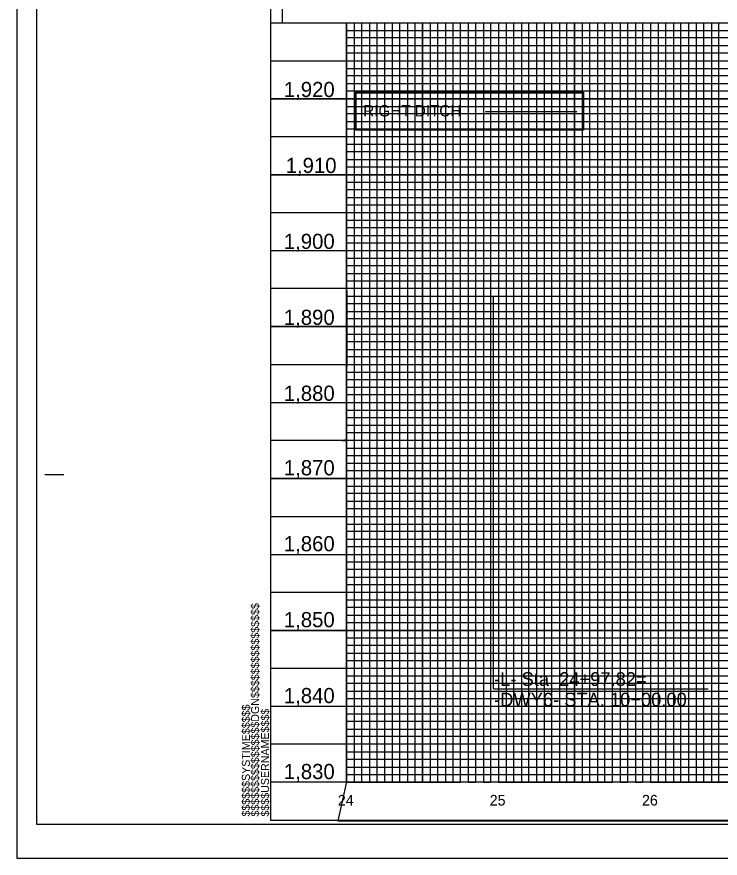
# Model space of a CAD drawing. Extents: x 557032 to 558716, y 513430 to 514605.
# Drawn here: x 557032 to 557495, y 513430 to 513984 of the extents above; entities that cross this region are included whole.
import ezdxf

# ---------------------------------------------------------------- set-up
doc = ezdxf.new("R2010")
doc.units = 0
for name, color, linetype in [('Exist Vertical Profile Horizontal Axis Label Major', 7, 'Continuous'), ('Exist Vertical Profile Vertical Axis Label', 7, 'Continuous'), ('Prop Grid Mask', 7, 'Continuous'), ('Prop PFL Ditch Label CELL', 7, 'Continuous'), ('Prop VPI Label', 7, 'Continuous'), ('Scratch_Level_5', 7, 'Continuous'), ('Sheet Cutting Line CELL', 7, 'Continuous'), ('Sheet DOT Grid CELL', 7, 'Continuous'), ('Sheet Layout Profile Border Port 2', 7, 'Continuous'), ('Sheet Plot Border Inside CELL', 7, 'Continuous'), ('Sheet Plot Border Outside CELL', 7, 'Continuous'), ('Sheet Profile CELL', 7, 'Continuous'), ('Sheet Profile Grid Major CELL', 7, 'Continuous'), ('Sheet Profile Grid Middle CELL', 7, 'Continuous'), ('Sheet Profile Grid Minor CELL', 7, 'Continuous')]:
    doc.layers.add(name, color=color, linetype=linetype)

msp = doc.modelspace()

# ---------------------------------------------------------------- linework, layer by layer
at = {"layer": 'Prop Grid Mask'}
msp.add_lwpolyline([(557255.39, 513934.64), (557405.39, 513934.64), (557405.39, 513909.64), (557255.39, 513909.64)], close=True, dxfattribs=at)
at = {"layer": 'Prop PFL Ditch Label CELL'}
for p, q in [((557255.39, 513919.64), (557255.39, 513919.64)), ((557340.94, 513921.99), (557400.94, 513921.99))]:
    msp.add_line(p, q, dxfattribs=at)
at = {"layer": 'Prop VPI Label'}
for q in [(557346.08, 513800.39), (557487.33, 513541.93)]:
    msp.add_line((557346.08, 513541.93), q, dxfattribs=at)
msp.add_lwpolyline([(557255.7, 513934.19), (557404.36, 513934.19), (557404.36, 513909.98), (557255.7, 513909.98)], close=True, dxfattribs=at)
at = {"layer": 'Scratch_Level_5'}
msp.add_line((557249.45, 513953.77), (557249.38, 513953.77), dxfattribs=at)
for points in [[(557207.08, 514505.4), (557207.08, 513980.4), (558649.45, 513980.4), (558649.45, 514344.35), (558499.4, 514344.35), (558499.4, 514505.4)], [(557249.45, 513960.4), (557249.45, 513809.09), (557249.45, 513808.44), (557249.5, 513800.29), (557249.4, 513708.16), (557249.4, 513480.77), (557243.76, 513454.91), (558646.31, 513455.07), (558649.46, 513648.82), (558649.45, 513648.95), (558649.45, 513655.65), (558652.01, 513799.51), (558499.4, 513799.35), (558499.4, 513960.4)]]:
    msp.add_lwpolyline(points, close=True, dxfattribs=at)
for points in [[(557249.38, 513953.77), (557249.48, 513844.15), (557249.43, 513801.01), (557249.45, 513705.73), (557246.58, 513705.4)], [(557246.58, 513705.4), (557249.45, 513705.4), (557249.45, 513953.77)]]:
    msp.add_lwpolyline(points, dxfattribs=at)
at = {"layer": 'Sheet Cutting Line CELL'}
for p, q in [((557032.45, 514530.4), (557032.45, 513430.4)), ((557032.45, 513430.4), (558716.45, 513430.4))]:
    msp.add_line(p, q, dxfattribs=at)
at = {"layer": 'Sheet DOT Grid CELL'}
for p, q in [((557199.45, 513980.4), (558699.34, 513980.4)), ((557249.45, 513980.4), (557249.45, 513480.4)), ((557299.45, 513980.4), (557299.45, 513480.4)), ((557349.45, 513980.4), (557349.45, 513480.4)), ((557399.45, 513980.4), (557399.45, 513480.4)), ((557449.45, 513980.4), (557449.45, 513480.4)), ((557249.45, 513953.77), (557249.45, 513482.78)), ((557299.45, 513953.77), (557299.45, 513484.02)), ((557349.45, 513953.77), (557349.45, 513484.06)), ((557399.45, 513953.77), (557399.45, 513484.1)), ((557449.45, 513953.77), (557449.45, 513484.13)), ((557199.45, 513930.4), (558699.34, 513930.4)), ((557205.68, 513930.4), (558692.7, 513930.4)), ((557199.45, 513880.4), (558699.34, 513880.4)), ((557205.25, 513880.4), (558692.98, 513880.4)), ((557199.45, 513830.4), (558699.34, 513830.4)), ((557204.83, 513830.4), (558693.26, 513830.4)), ((557199.45, 513780.4), (558699.34, 513780.4)), ((557204.41, 513780.4), (558693.53, 513780.4)), ((557199.45, 513730.4), (558699.34, 513730.4)), ((557203.99, 513730.4), (558693.81, 513730.4)), ((557199.45, 513680.4), (558699.34, 513680.4)), ((557203.57, 513680.4), (558694.09, 513680.4)), ((557199.45, 513630.4), (558699.34, 513630.4)), ((557203.15, 513630.4), (558694.37, 513630.4)), ((557199.45, 513580.4), (558699.34, 513580.4)), ((557202.73, 513580.4), (558694.65, 513580.4)), ((557199.45, 513530.4), (558699.34, 513530.4)), ((557202.31, 513530.4), (558694.93, 513530.4))]:
    msp.add_line(p, q, dxfattribs=at)
at = {"layer": 'Sheet Layout Profile Border Port 2'}
msp.add_lwpolyline([(557249.45, 513980.4), (558649.45, 513980.4), (558649.45, 513480.4), (557249.45, 513480.4)], close=True, dxfattribs=at)
at = {"layer": 'Sheet Plot Border Inside CELL'}
msp.add_lwpolyline([(557045.45, 513452.85), (558711.95, 513452.85), (558711.95, 514507.95), (557045.45, 514507.95)], close=True, dxfattribs=at)
at = {"layer": 'Sheet Plot Border Outside CELL'}
msp.add_lwpolyline([(557032.45, 513430.4), (558716.45, 513430.4), (558716.45, 514530.4), (557032.45, 514530.4)], close=True, dxfattribs=at)
at = {"layer": 'Sheet Profile CELL'}
for p, q in [((557199.45, 513980.4), (558699.45, 513980.4)), ((557050.95, 513682.9), (557063.45, 513682.9)), ((558699.45, 513480.4), (557199.45, 513480.4)), ((557199.45, 513455.4), (558699.45, 513455.4)), ((557199.45, 513455.4), (557199.45, 513455.4)), ((557199.45, 513455.4), (557199.45, 513455.4)), ((557199.45, 513455.4), (557199.45, 513455.4)), ((557199.45, 513455.4), (557199.45, 513455.4)), ((557199.45, 513455.4), (557199.45, 513455.4)), ((557199.45, 513455.4), (557199.45, 513455.4)), ((557199.45, 513455.4), (557199.45, 513455.4))]:
    msp.add_line(p, q, dxfattribs=at)
msp.add_lwpolyline([(558699.45, 514505.4), (557199.45, 514505.4), (557199.45, 513455.4), (558699.45, 513455.4)], close=True, dxfattribs=at)
msp.add_lwpolyline([(557236.95, 513455.4), (557236.95, 513455.4)], dxfattribs=at)
at = {"layer": 'Sheet Profile Grid Major CELL'}
msp.add_line((557199.45, 513480.4), (557199.45, 513480.4), dxfattribs=at)
for points in [[(557249.45, 513980.4), (557249.45, 513480.4), (557299.45, 513480.4), (557299.45, 513980.4), (557349.45, 513980.4), (557349.45, 513480.4), (557399.45, 513480.4), (557399.45, 513980.4), (557449.45, 513980.4), (557449.45, 513480.4), (557499.45, 513480.4)], [(557249.45, 513953.77), (557249.45, 513482.78)], [(557299.45, 513484.02), (557299.45, 513953.77)], [(557349.45, 513953.77), (557349.45, 513484.06)], [(557399.45, 513484.1), (557399.45, 513953.77)], [(557449.45, 513953.77), (557449.45, 513484.13)], [(558699.45, 513930.4), (557199.45, 513930.4)], [(558692.7, 513930.4), (557205.68, 513930.4)], [(558699.45, 513880.4), (557199.45, 513880.4), (557199.45, 513830.4), (558699.45, 513830.4)], [(558692.98, 513880.4), (557205.25, 513880.4)], [(557204.83, 513830.4), (558693.26, 513830.4)], [(558699.45, 513780.4), (557199.45, 513780.4), (557199.45, 513730.4), (558699.45, 513730.4)], [(558693.53, 513780.4), (557204.41, 513780.4)], [(557203.99, 513730.4), (558693.81, 513730.4)], [(558699.45, 513680.4), (557199.45, 513680.4), (557199.45, 513630.4), (558529.45, 513630.4)], [(558694.09, 513680.4), (557203.57, 513680.4)], [(557203.15, 513630.4), (558529.45, 513630.4)], [(558699.45, 513580.4), (557199.45, 513580.4), (557199.45, 513580.4), (557199.45, 513530.4), (558699.45, 513530.4)], [(558694.65, 513580.4), (557202.73, 513580.4)], [(557202.31, 513530.4), (558694.93, 513530.4)], [(558699.45, 513480.4), (557199.45, 513480.4)]]:
    msp.add_lwpolyline(points, dxfattribs=at)
at = {"layer": 'Sheet Profile Grid Middle CELL'}
for points in [[(557224.45, 513980.4), (557274.45, 513980.4), (557274.45, 513480.4), (557324.45, 513480.4), (557324.45, 513980.4), (557374.45, 513980.4), (557374.45, 513480.4), (557424.45, 513480.4), (557424.45, 513980.4), (557474.45, 513980.4), (557474.45, 513480.4), (557524.45, 513480.4)], [(557199.45, 513955.4), (558699.45, 513955.4)], [(557274.45, 513953.77), (557274.45, 513484)], [(557324.45, 513484.04), (557324.45, 513953.77)], [(557374.45, 513953.77), (557374.45, 513484.08)], [(557424.45, 513484.11), (557424.45, 513953.77)], [(557474.45, 513953.77), (557474.45, 513484.15)], [(558699.45, 513905.4), (557199.45, 513905.4), (557199.45, 513855.4), (558699.45, 513855.4)], [(558692.84, 513905.4), (557205.47, 513905.4)], [(557205.04, 513855.4), (558693.12, 513855.4)], [(558699.45, 513805.4), (557199.45, 513805.4), (557199.45, 513755.4), (558699.45, 513755.4)], [(558693.39, 513805.4), (557204.62, 513805.4)], [(557204.2, 513755.4), (558693.67, 513755.4)], [(558699.45, 513705.4), (557199.45, 513705.4), (557199.45, 513655.4), (558699.45, 513655.4)], [(558693.95, 513705.4), (557203.78, 513705.4)], [(557203.36, 513655.4), (558694.23, 513655.4)], [(558699.45, 513605.4), (557199.45, 513605.4), (557199.45, 513555.4), (558699.45, 513555.4)], [(558694.51, 513605.4), (557202.94, 513605.4)], [(557202.52, 513555.4), (558694.79, 513555.4)], [(558699.45, 513505.4), (557199.45, 513505.4)], [(558450.15, 513505.4), (557202.1, 513505.4)]]:
    msp.add_lwpolyline(points, dxfattribs=at)
at = {"layer": 'Sheet Profile Grid Minor CELL'}
for p, q in [((557249.45, 513975.4), (558649.45, 513975.4)), ((558649.45, 513970.4), (557249.45, 513970.4)), ((557249.45, 513965.4), (558649.45, 513965.4)), ((558649.45, 513960.4), (557249.45, 513960.4)), ((557249.45, 513950.4), (558649.45, 513950.4)), ((557249.45, 513950.4), (558649.45, 513950.4)), ((558649.45, 513945.4), (557249.45, 513945.4)), ((558649.45, 513945.4), (557249.45, 513945.4)), ((557249.45, 513940.4), (558649.45, 513940.4)), ((557249.45, 513940.4), (558649.45, 513940.4)), ((558649.45, 513935.4), (557249.45, 513935.4)), ((558649.45, 513935.4), (557249.45, 513935.4)), ((557249.45, 513925.4), (558649.45, 513925.4)), ((557249.45, 513925.4), (558649.45, 513925.4)), ((558649.45, 513920.4), (557249.45, 513920.4)), ((558649.45, 513920.4), (557249.45, 513920.4)), ((557249.45, 513915.4), (558649.45, 513915.4)), ((557249.45, 513915.4), (558649.45, 513915.4)), ((558649.45, 513910.4), (557249.45, 513910.4)), ((558649.45, 513910.4), (557249.45, 513910.4)), ((557249.45, 513900.4), (558649.45, 513900.4)), ((557249.45, 513900.4), (558649.45, 513900.4)), ((558649.45, 513895.4), (557249.45, 513895.4)), ((558649.45, 513895.4), (557249.45, 513895.4)), ((557249.45, 513890.4), (558649.45, 513890.4)), ((557249.45, 513890.4), (558649.45, 513890.4)), ((558649.45, 513885.4), (557249.45, 513885.4)), ((558649.45, 513885.4), (557249.45, 513885.4)), ((557249.45, 513875.4), (558649.45, 513875.4)), ((557249.45, 513875.4), (558649.45, 513875.4)), ((558649.45, 513870.4), (557249.45, 513870.4)), ((558649.45, 513870.4), (557249.45, 513870.4)), ((557249.45, 513865.4), (558649.45, 513865.4)), ((557249.45, 513865.4), (558649.45, 513865.4)), ((558649.45, 513860.4), (557249.45, 513860.4)), ((558649.45, 513860.4), (557249.45, 513860.4)), ((557249.45, 513850.4), (558649.45, 513850.4)), ((557249.45, 513850.4), (558649.45, 513850.4)), ((558649.45, 513845.4), (557249.45, 513845.4)), ((558649.45, 513845.4), (557249.45, 513845.4)), ((557249.45, 513840.4), (558649.45, 513840.4)), ((557249.45, 513840.4), (558649.45, 513840.4)), ((558649.45, 513835.4), (557249.45, 513835.4)), ((558649.45, 513835.4), (557249.45, 513835.4)), ((557249.45, 513825.4), (558649.45, 513825.4)), ((557249.45, 513825.4), (558649.45, 513825.4)), ((558649.45, 513820.4), (557249.45, 513820.4)), ((558649.45, 513820.4), (557249.45, 513820.4)), ((557249.45, 513815.4), (558649.45, 513815.4)), ((557249.45, 513815.4), (558649.45, 513815.4)), ((558649.45, 513810.4), (557249.45, 513810.4)), ((558649.45, 513810.4), (557249.45, 513810.4)), ((557249.45, 513800.4), (558649.45, 513800.4)), ((557249.45, 513800.4), (558649.45, 513800.4)), ((558649.45, 513795.4), (557249.45, 513795.4)), ((558649.45, 513795.4), (557249.45, 513795.4)), ((557249.45, 513790.4), (558649.45, 513790.4)), ((557249.45, 513790.4), (558649.45, 513790.4)), ((558649.45, 513785.4), (557249.45, 513785.55)), ((558649.45, 513785.4), (557249.45, 513785.55)), ((557249.45, 513775.4), (558649.45, 513775.4)), ((557249.45, 513775.4), (558649.45, 513775.4)), ((558649.45, 513770.4), (557249.45, 513770.4)), ((558649.45, 513770.4), (557249.45, 513770.4)), ((557249.45, 513765.4), (558649.45, 513765.4)), ((557249.45, 513765.4), (558649.45, 513765.4)), ((558649.45, 513760.4), (557249.45, 513760.4)), ((558649.45, 513760.4), (557249.45, 513760.4)), ((557249.45, 513750.4), (558649.45, 513750.4)), ((557249.45, 513750.4), (558649.45, 513750.4)), ((558649.45, 513745.4), (557249.45, 513745.4)), ((558649.45, 513745.4), (557249.45, 513745.4)), ((557249.45, 513740.4), (558649.45, 513740.4)), ((557249.45, 513740.4), (558649.45, 513740.4)), ((558649.45, 513735.4), (557249.45, 513735.4)), ((558649.45, 513735.4), (557249.45, 513735.4)), ((557249.45, 513725.4), (558649.45, 513725.4)), ((557249.45, 513725.4), (558649.45, 513725.4)), ((558649.45, 513720.4), (557249.45, 513720.4)), ((558649.45, 513720.4), (557249.45, 513720.4)), ((557249.45, 513715.4), (558649.45, 513715.4)), ((557249.45, 513715.4), (558649.45, 513715.4)), ((558649.45, 513710.4), (557249.45, 513710.4)), ((558649.45, 513710.4), (557249.45, 513710.4)), ((557249.45, 513700.4), (558649.45, 513700.4)), ((557249.45, 513700.4), (558649.45, 513700.4)), ((558649.45, 513695.4), (557249.45, 513695.4)), ((558649.45, 513695.4), (557249.45, 513695.4)), ((557249.45, 513690.4), (558649.45, 513690.4)), ((557249.45, 513690.4), (558649.45, 513690.4)), ((558649.45, 513685.4), (557249.45, 513685.4)), ((558649.45, 513685.4), (557249.45, 513685.4)), ((557249.45, 513675.4), (558649.45, 513675.4)), ((557249.45, 513675.4), (558649.45, 513675.4)), ((558649.45, 513670.4), (557249.45, 513670.4)), ((558649.45, 513670.4), (557249.45, 513670.4)), ((557249.45, 513665.4), (558649.45, 513665.4)), ((557249.45, 513665.4), (558649.45, 513665.4)), ((558649.45, 513660.4), (557249.45, 513660.4)), ((558649.45, 513660.4), (557249.45, 513660.4)), ((557249.45, 513650.4), (558649.45, 513650.4)), ((557249.45, 513650.4), (558649.45, 513650.4)), ((558529.45, 513645.4), (557249.45, 513645.4)), ((558529.45, 513645.4), (557249.45, 513645.4)), ((557249.45, 513640.4), (558529.45, 513640.4)), ((557249.45, 513640.4), (558529.45, 513640.4)), ((558529.45, 513635.4), (557249.45, 513635.4)), ((558529.45, 513635.4), (557249.45, 513635.4)), ((557249.45, 513625.4), (558529.45, 513625.4)), ((557249.45, 513625.4), (558529.45, 513625.4)), ((558649.45, 513620.4), (557249.45, 513620.4)), ((558649.45, 513620.4), (557249.45, 513620.4)), ((557249.45, 513615.4), (558649.45, 513615.4)), ((557249.45, 513615.4), (558649.45, 513615.4)), ((558649.45, 513610.4), (557249.45, 513610.4)), ((558649.45, 513610.4), (557249.45, 513610.4)), ((557249.45, 513600.4), (558649.45, 513600.4)), ((557249.45, 513600.4), (558649.45, 513600.4)), ((558649.45, 513595.4), (557249.45, 513595.4)), ((558649.45, 513595.4), (557249.45, 513595.4)), ((557249.45, 513590.4), (558649.45, 513590.4)), ((557249.45, 513590.4), (558649.45, 513590.4)), ((558649.45, 513585.4), (557249.45, 513585.4)), ((558649.45, 513585.4), (557249.45, 513585.4)), ((557249.45, 513575.4), (558649.45, 513575.4)), ((557249.45, 513575.4), (558649.45, 513575.4)), ((558649.45, 513570.4), (557249.45, 513570.4)), ((558649.45, 513570.4), (557249.45, 513570.4)), ((557249.45, 513565.4), (558649.45, 513565.4)), ((557249.45, 513565.4), (558649.45, 513565.4)), ((558649.45, 513560.4), (557249.45, 513560.4)), ((558649.45, 513560.4), (557249.45, 513560.4)), ((557249.45, 513550.4), (558649.45, 513550.4)), ((557249.45, 513550.4), (558649.45, 513550.4)), ((558649.45, 513545.4), (557249.45, 513545.4)), ((558649.45, 513545.4), (557249.45, 513545.4)), ((557249.45, 513540.4), (558649.45, 513540.4)), ((557249.45, 513540.4), (558649.45, 513540.4)), ((558649.45, 513535.4), (557249.45, 513535.4)), ((558649.45, 513535.4), (557249.45, 513535.4)), ((557249.45, 513525.4), (558649.45, 513525.4)), ((557249.45, 513525.4), (558649.45, 513525.4)), ((558649.45, 513520.4), (557249.45, 513520.4)), ((558649.45, 513520.4), (557249.45, 513520.4)), ((557249.45, 513515.4), (558649.45, 513515.4)), ((557249.45, 513515.4), (558649.45, 513515.4)), ((558649.45, 513510.4), (557249.45, 513510.4)), ((558649.45, 513510.4), (557249.45, 513510.4)), ((557249.45, 513500.4), (558649.45, 513500.4)), ((557249.45, 513500.4), (558446.89, 513500.4)), ((558649.45, 513495.4), (557249.45, 513495.4)), ((558443.62, 513495.4), (557249.45, 513495.4)), ((557249.45, 513490.4), (558649.45, 513490.4)), ((557249.45, 513490.4), (558440.36, 513490.4)), ((557249.45, 513485.4), (558649.45, 513485.4)), ((557249.45, 513485.4), (558437.1, 513485.4))]:
    msp.add_line(p, q, dxfattribs=at)
for points in [[(557249.45, 513980.4), (557254.45, 513980.4), (557254.45, 513480.4), (557259.45, 513480.4), (557259.45, 513980.4), (557264.45, 513980.4), (557264.45, 513480.4), (557269.45, 513480.4), (557269.45, 513980.4), (557279.45, 513980.4), (557279.45, 513480.4), (557284.45, 513480.4), (557284.45, 513980.4), (557289.45, 513980.4), (557289.45, 513480.4), (557294.45, 513480.4), (557304.45, 513480.4), (557309.45, 513480.4), (557309.45, 513980.4), (557314.45, 513980.4), (557314.45, 513480.4), (557319.45, 513480.4), (557319.45, 513980.4), (557329.45, 513980.4), (557329.45, 513480.4), (557334.45, 513480.4), (557334.45, 513980.4), (557339.45, 513980.4), (557339.45, 513480.4), (557344.45, 513480.4), (557344.45, 513980.4), (557354.45, 513980.4), (557354.45, 513480.4), (557359.45, 513480.4), (557359.45, 513980.4), (557364.45, 513980.4), (557364.45, 513480.4), (557369.45, 513480.4), (557369.45, 513980.4), (557379.45, 513980.4), (557379.45, 513480.4), (557384.45, 513480.4), (557384.45, 513980.4), (557389.45, 513980.4), (557389.45, 513480.4), (557394.45, 513480.4), (557394.45, 513980.4), (557404.45, 513980.4), (557404.45, 513480.4), (557409.45, 513480.4), (557409.45, 513980.4), (557414.45, 513980.4), (557414.45, 513480.4), (557419.45, 513480.4), (557419.45, 513980.4), (557429.45, 513980.4), (557429.45, 513480.4), (557434.45, 513480.4), (557434.45, 513980.4), (557439.45, 513980.4), (557439.45, 513480.4), (557444.45, 513480.4), (557444.45, 513980.4), (557454.45, 513980.4), (557454.45, 513480.4), (557459.45, 513480.4), (557459.45, 513980.4), (557464.45, 513980.4), (557464.45, 513480.4)], [(557294.45, 513480.4), (557294.45, 513980.4), (557304.45, 513980.4), (557304.45, 513480.4)], [(557464.45, 513480.4), (557469.45, 513480.4), (557469.45, 513980.4), (557479.45, 513980.4), (557479.45, 513480.4), (557484.45, 513480.4), (557484.45, 513980.4), (557489.45, 513980.4), (557489.45, 513480.4), (557494.45, 513480.4), (557494.45, 513980.4), (557504.45, 513980.4)], [(557254.45, 513953.77), (557254.45, 513483.41)], [(557259.45, 513483.99), (557259.45, 513953.77)], [(557264.45, 513953.77), (557264.45, 513483.99)], [(557269.45, 513483.99), (557269.45, 513953.77)], [(557279.45, 513953.77), (557279.45, 513484)], [(557284.45, 513484.01), (557284.45, 513953.77)], [(557289.45, 513953.77), (557289.45, 513484.01)], [(557294.45, 513484.01), (557294.45, 513953.77)], [(557304.45, 513953.77), (557304.45, 513484.02)], [(557309.45, 513484.02), (557309.45, 513953.77)], [(557314.45, 513953.77), (557314.45, 513484.03)], [(557319.45, 513484.03), (557319.45, 513953.77)], [(557329.45, 513953.77), (557329.45, 513484.04)], [(557334.45, 513484.04), (557334.45, 513953.77)], [(557339.45, 513953.77), (557339.45, 513484.05)], [(557344.45, 513484.05), (557344.45, 513953.77)], [(557354.45, 513953.77), (557354.45, 513484.06)], [(557359.45, 513484.06), (557359.45, 513953.77)], [(557364.45, 513953.77), (557364.45, 513484.07)], [(557369.45, 513484.07), (557369.45, 513953.77)], [(557379.45, 513953.77), (557379.45, 513484.08)], [(557384.45, 513484.08), (557384.45, 513953.77)], [(557389.45, 513953.77), (557389.45, 513484.09)], [(557394.45, 513484.09), (557394.45, 513953.77)], [(557404.45, 513953.77), (557404.45, 513484.1)], [(557409.45, 513484.1), (557409.45, 513953.77)], [(557414.45, 513953.77), (557414.45, 513484.11)], [(557419.45, 513484.11), (557419.45, 513953.77)], [(557429.45, 513953.77), (557429.45, 513484.12)], [(557434.45, 513484.12), (557434.45, 513953.77)], [(557439.45, 513953.77), (557439.45, 513484.13)], [(557444.45, 513484.13), (557444.45, 513953.77)], [(557454.45, 513953.77), (557454.45, 513484.14)], [(557459.45, 513484.14), (557459.45, 513953.77)], [(557464.45, 513953.77), (557464.45, 513484.15)], [(557469.45, 513484.15), (557469.45, 513953.77)], [(557479.45, 513953.77), (557479.45, 513484.16)], [(557484.45, 513484.16), (557484.45, 513953.77)], [(557489.45, 513953.77), (557489.45, 513484.17)], [(557494.45, 513484.17), (557494.45, 513953.77)]]:
    msp.add_lwpolyline(points, dxfattribs=at)

# ---------------------------------------------------------------- texts
at = {"layer": 'Exist Vertical Profile Horizontal Axis Label Major'}
for s, p in [('24', (557243.68, 513465.04)), ('25', (557343.61, 513465.04)), ('26', (557443.81, 513465.04))]:
    msp.add_text(s, height=7, dxfattribs=at).set_placement(p)
at = {"layer": 'Exist Vertical Profile Vertical Axis Label'}
for s, p in [('1,920', (557208.15, 513931.5)), ('1,920', (557208.15, 513931.5)), ('1,920', (557208.15, 513931.5)), ('1,920', (557208.15, 513931.5)), ('1,910', (557209.35, 513881.5)), ('1,910', (557209.35, 513881.5)), ('1,910', (557209.35, 513881.5)), ('1,910', (557209.35, 513881.5)), ('1,900', (557208.15, 513831.5)), ('1,900', (557208.15, 513831.5)), ('1,900', (557208.15, 513831.5)), ('1,900', (557208.15, 513831.5)), ('1,890', (557208.15, 513781.5)), ('1,890', (557208.15, 513781.5)), ('1,890', (557208.15, 513781.5)), ('1,890', (557208.15, 513781.5)), ('1,880', (557208.15, 513731.5)), ('1,880', (557208.15, 513731.5)), ('1,880', (557208.15, 513731.5)), ('1,880', (557208.15, 513731.5)), ('1,870', (557208.15, 513682.45)), ('1,870', (557208.15, 513682.45)), ('1,860', (557208.15, 513632.45)), ('1,860', (557208.15, 513632.45)), ('1,850', (557208.15, 513582.45)), ('1,850', (557208.15, 513582.45)), ('1,840', (557208.15, 513532.45)), ('1,840', (557208.15, 513532.45)), ('1,830', (557208.15, 513482.45)), ('1,830', (557208.15, 513482.45))]:
    msp.add_text(s, height=10, dxfattribs=at).set_placement(p)
at = {"layer": 'Prop PFL Ditch Label CELL'}
msp.add_text('RIGHT DITCH', height=7.485, dxfattribs=at).set_placement((557260.39, 513918.74))
at = {"layer": 'Prop VPI Label'}
for s, p in [('-L- Sta. 24+97.82=', (557346.51, 513543.84)), ('-DWY6- STA. 10+00.00', (557346.51, 513530.34))]:
    msp.add_text(s, height=9, dxfattribs=at).set_placement(p)
at = {"layer": 'Sheet Profile CELL'}
for s, p in [('$$$$$$$$$$$$$$$$DGN$$$$$$$$$$$$$$$$', (557191.82, 513457.78)), ('$$$$$$SYSTIME$$$$$', (557185.77, 513457.78)), ('$$$$USERNAME$$$$', (557198.39, 513457.79))]:
    msp.add_text(s, height=5.25, rotation=90, dxfattribs=at).set_placement(p)

doc.saveas('drawing.dxf')
